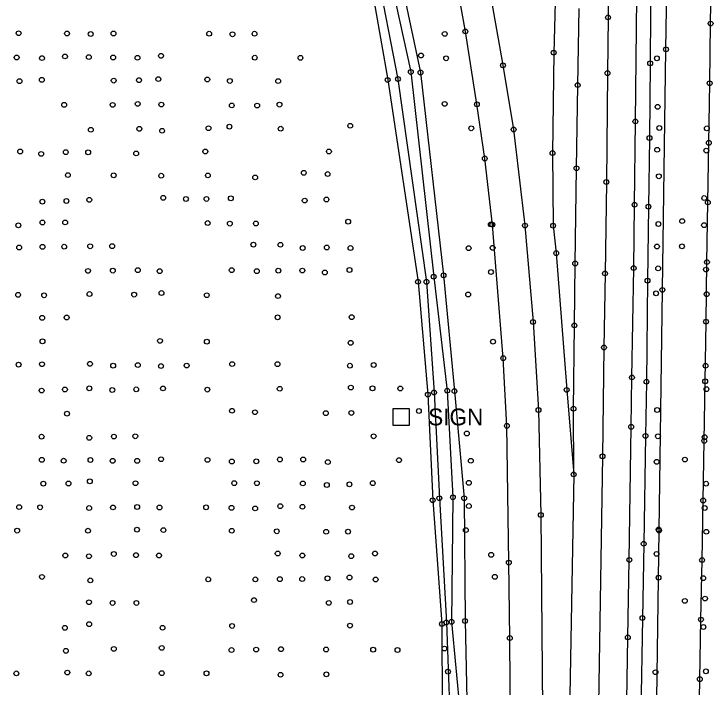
# Model space of a CAD drawing. Extents: x 20503438 to 20508873, y 7964251 to 7984667.
# Drawn here: x 20506370.9 to 20506661.3, y 7969202.7 to 7969482.5 of the extents above; entities that cross this region are included whole.
import ezdxf

# ---------------------------------------------------------------- set-up
doc = ezdxf.new("R2010")
doc.units = 0
for name, color, linetype in [('SurBreakLine', 7, 'Continuous'), ('SurConcreteSlab', 7, 'Continuous'), ('SurDrainageArrowDown', 7, 'Continuous'), ('SurDrainageArrowUp', 7, 'Continuous'), ('SurEdgeRoadPaved', 7, 'Continuous'), ('SurEdgeShoulderPaved', 7, 'Continuous'), ('SurGuardRailCable', 7, 'Continuous'), ('SurPointsNonDTM', 7, 'Continuous'), ('SurRoadPoints', 7, 'Continuous'), ('SurSurveyPoints', 7, 'Continuous')]:
    doc.layers.add(name, color=color, linetype=linetype)

msp = doc.modelspace()

# ---------------------------------------------------------------- linework, layer by layer
at = {"layer": 'SurBreakLine'}
for points in [[(20506618.14, 7969523.36), (20506617.67, 7969481.03), (20506617.43, 7969457.83), (20506616.96, 7969412.61), (20506616.41, 7969374.63), (20506615.97, 7969343.84), (20506615.38, 7969298.61), (20506613.68, 7969195.48), (20506612.84, 7969147.98), (20506612.67, 7969139.02), (20506612.29, 7969096.34), (20506611.74, 7969045.72), (20506611.38, 7969017.5), (20506610.7, 7968975.24), (20506609.9, 7968927.43)], [(20506526.38, 7969501.4), (20506535.77, 7969458.35), (20506545.25, 7969373.27), (20506550.88, 7969325.87), (20506553.23, 7969281.58), (20506552.68, 7969229.8), (20506556.22, 7969191.53), (20506555.93, 7969123.81), (20506558.38, 7969055.03)], [(20506530.55, 7969501.87), (20506539.77, 7969458.14), (20506549.36, 7969373.83), (20506553.86, 7969325.71), (20506557.91, 7969281.18), (20506558.28, 7969230.17), (20506559.1, 7969190.68), (20506560.16, 7969121.72), (20506560.98, 7969054.99)], [(20506518.36, 7969500.09), (20506526.15, 7969455.03), (20506538.74, 7969371.16), (20506542.8, 7969324.25), (20506544.83, 7969280.33), (20506548.66, 7969228.93), (20506548.82, 7969193.76), (20506548.24, 7969123.29), (20506548.83, 7969054.45)]]:
    msp.add_lwpolyline(points, dxfattribs=at)
at = {"layer": 'SurConcreteSlab'}
msp.add_lwpolyline([(20506564.49, 7969514.44), (20506574.01, 7969461.11), (20506578.45, 7969434.44), (20506583.17, 7969394.51), (20506586.51, 7969354.44), (20506588.8, 7969317.85), (20506589.77, 7969274.23), (20506590.63, 7969177.23), (20506591.64, 7969086.12), (20506591.92, 7969027.98), (20506592.58, 7968959.05), (20506592.8, 7968932.21), (20506593.59, 7968825.07), (20506593.73, 7968776.04), (20506594.33, 7968740.28), (20506595.27, 7968683.67)], dxfattribs=at)
at = {"layer": 'SurDrainageArrowDown'}
msp.add_lwpolyline([(20506653.71, 7968931.94), (20506653.76, 7968956.94), (20506653.81, 7968981.94), (20506653.87, 7969006.94), (20506653.92, 7969031.94), (20506653.97, 7969056.94), (20506654.02, 7969081.94), (20506654.08, 7969106.94), (20506654.43, 7969131.75), (20506654.89, 7969156.5), (20506655.35, 7969181.25), (20506655.81, 7969206), (20506656.26, 7969230.74), (20506656.72, 7969255.49), (20506657.18, 7969280.24), (20506657.62, 7969305), (20506658, 7969329.78), (20506658.38, 7969354.56), (20506658.75, 7969379.34), (20506659.13, 7969404.12), (20506659.51, 7969428.89), (20506659.89, 7969453.67), (20506660.27, 7969478.45), (20506660.63, 7969503.23)], dxfattribs=at)
at = {"layer": 'SurDrainageArrowUp'}
msp.add_lwpolyline([(20506438.1, 7969771.83), (20506443.35, 7969742.94), (20506462.68, 7969706.4), (20506478.32, 7969662.6), (20506496.28, 7969609.97), (20506512.32, 7969564.26), (20506521.33, 7969501.72), (20506530.41, 7969455.42), (20506542.25, 7969371.11), (20506545.39, 7969325.12), (20506547.61, 7969281.18), (20506550.51, 7969229.55), (20506551.89, 7969191.24), (20506551.28, 7969123.71), (20506552.43, 7969055.04)], dxfattribs=at)
at = {"layer": 'SurEdgeRoadPaved'}
for points in [[(20506621.49, 7968907.38), (20506621.92, 7968945.44), (20506622.44, 7968976.48), (20506623.13, 7969015.52), (20506623.63, 7969053.1), (20506623.96, 7969082.25), (20506624.47, 7969121.99), (20506624.91, 7969159.97), (20506625.3, 7969188.54), (20506625.87, 7969223.35), (20506626.51, 7969255.54), (20506627.28, 7969310.85), (20506627.6, 7969331.39), (20506628.32, 7969376.84), (20506628.68, 7969403.15), (20506629.02, 7969437.79), (20506629.57, 7969489.48)], [(20506595.72, 7969487.19), (20506595.11, 7969466.36), (20506594.59, 7969424.65), (20506594.85, 7969394.48), (20506596.15, 7969383.03), (20506600.49, 7969326.21), (20506603.4, 7969291.1), (20506600.36, 7969122.74), (20506600.06, 7969086.76), (20506599.49, 7969053.21), (20506599.36, 7969019.14), (20506598.62, 7968981.46), (20506598.4, 7968961.23), (20506597.81, 7968911.23), (20506596.74, 7968813.5), (20506596.12, 7968772.39), (20506595.63, 7968706.72), (20506595.11, 7968672.96), (20506595.06, 7968637.97), (20506594.54, 7968602.04), (20506594.11, 7968535.15), (20506593.63, 7968499.17)], [(20506603.4, 7969291.1), (20506603.32, 7969318.39), (20506603.68, 7969353.03), (20506604.02, 7969378.75), (20506604.55, 7969418.34), (20506605.06, 7969452.89), (20506605.62, 7969484.73)]]:
    msp.add_lwpolyline(points, dxfattribs=at)
at = {"layer": 'SurEdgeShoulderPaved'}
for points in [[(20506579.21, 7968920.08), (20506580.04, 7968948.94), (20506578.13, 7968975.95), (20506578.51, 7968997.69), (20506578.2, 7969027.13), (20506578.68, 7969043.72), (20506578.97, 7969057.63), (20506578.72, 7969080.47), (20506578.43, 7969086.41), (20506578.28, 7969089.38), (20506577.4, 7969107.2), (20506577.45, 7969146.63), (20506576.88, 7969223.07), (20506576.47, 7969254.43), (20506575.66, 7969311.26), (20506574.14, 7969339.42), (20506569.62, 7969394.88), (20506566.46, 7969422.38), (20506563.2, 7969444.91), (20506558.41, 7969475.22), (20506553.3, 7969503.59)], [(20506635.48, 7969504.27), (20506635.15, 7969461.94), (20506634.88, 7969430.9), (20506634.45, 7969402.36), (20506634.07, 7969371.62), (20506633.61, 7969329.61), (20506633.23, 7969307.1), (20506632.49, 7969262.27), (20506631.93, 7969231.4), (20506631.34, 7969191.98), (20506630.67, 7969146.89), (20506630.47, 7969127.19), (20506630.23, 7969104.68), (20506629.72, 7969073.79), (20506629.37, 7969033.53), (20506628.89, 7969008.02), (20506628.37, 7968979.45), (20506627.76, 7968942.11), (20506627.2, 7968902.1)]]:
    msp.add_lwpolyline(points, dxfattribs=at)
at = {"layer": 'SurGuardRailCable'}
msp.add_lwpolyline([(20506628.76, 7968467.84), (20506630.09, 7968567.83), (20506631.3, 7968667.82), (20506632.48, 7968767.82), (20506633.65, 7968867.81), (20506634.84, 7968967.8), (20506636.09, 7969067.8), (20506637.47, 7969167.79), (20506638.85, 7969267.78), (20506640.24, 7969367.77), (20506641.73, 7969467.75), (20506642.19, 7969501.7)], dxfattribs=at)
at = {"layer": 'SurPointsNonDTM'}
for centre in [(20506641.73, 7969467.75), (20506640.24, 7969367.77), (20506638.85, 7969267.78)]:
    msp.add_circle(centre, 1, dxfattribs=at)
at = {"layer": 'SurRoadPoints'}
msp.add_lwpolyline([(20506531.77, 7969311.54), (20506531.77, 7969311.54), (20506535.2, 7969311.54), (20506535.2, 7969318.4), (20506528.34, 7969318.4), (20506528.34, 7969311.54), (20506531.77, 7969311.54)], dxfattribs=at)
at = {"layer": 'SurSurveyPoints'}
for centre in [(20506617.67, 7969481.03), (20506660.27, 7969478.45), (20506372.86, 7969474.45), (20506392.97, 7969474.34), (20506402.8, 7969474.12), (20506412.25, 7969474.33), (20506452, 7969474.25), (20506461.71, 7969474.02), (20506470.86, 7969474.24), (20506549.84, 7969474.17), (20506558.41, 7969475.22), (20506392.12, 7969464.8), (20506402.03, 7969464.53), (20506432.01, 7969465.04), (20506539.97, 7969465.21), (20506595.11, 7969466.36), (20506372.06, 7969464.36), (20506382.58, 7969464.12), (20506412.14, 7969464.37), (20506422.22, 7969464.26), (20506470.93, 7969464.27), (20506489.91, 7969464.21), (20506550.4, 7969464.03), (20506635.15, 7969461.94), (20506637.97, 7969464.01), (20506574.01, 7969461.11), (20506535.77, 7969458.35), (20506539.77, 7969458.14), (20506617.43, 7969457.83), (20506373.21, 7969454.53), (20506382.51, 7969455.1), (20506412.36, 7969454.76), (20506422.87, 7969454.93), (20506430.9, 7969455.38), (20506451.22, 7969455.2), (20506460.6, 7969454.61), (20506480.67, 7969454.56), (20506526.15, 7969455.03), (20506530.41, 7969455.42), (20506605.06, 7969452.89), (20506659.89, 7969453.67), (20506391.79, 7969444.71), (20506411.91, 7969444.66), (20506422.32, 7969445.07), (20506432.13, 7969444.79), (20506461.39, 7969444.45), (20506471.95, 7969444.38), (20506481.2, 7969444.78), (20506549.82, 7969445.08), (20506563.2, 7969444.91), (20506638.26, 7969443.84), (20506460.41, 7969435.61), (20506510.6, 7969436), (20506629.02, 7969437.79), (20506402.86, 7969434.33), (20506422.98, 7969434.72), (20506432.45, 7969433.92), (20506451.71, 7969434.97), (20506481.71, 7969434.76), (20506560.86, 7969434.94), (20506578.45, 7969434.44), (20506638.96, 7969435.07), (20506658.72, 7969434.9), (20506634.88, 7969430.9), (20506659.51, 7969428.89), (20506373.52, 7969425.3), (20506382.23, 7969424.3), (20506392.44, 7969425.01), (20506401.73, 7969424.94), (20506421.69, 7969424.5), (20506450.42, 7969425.31), (20506501.74, 7969425.31), (20506594.59, 7969424.65), (20506638.09, 7969426.01), (20506658.48, 7969425.66), (20506566.46, 7969422.38), (20506604.55, 7969418.34), (20506393.33, 7969415.49), (20506412.34, 7969415.4), (20506432.09, 7969415.22), (20506451.48, 7969415.35), (20506491.28, 7969416.44), (20506501.2, 7969415.92), (20506471.11, 7969414.51), (20506616.96, 7969412.61), (20506638.78, 7969414.99), (20506382.73, 7969404.45), (20506392.71, 7969404.73), (20506402.21, 7969405.21), (20506432.92, 7969406.04), (20506442.35, 7969405.56), (20506450.86, 7969405.58), (20506461.01, 7969405.84), (20506491.68, 7969404.9), (20506500.7, 7969405.33), (20506657.62, 7969405.94), (20506659.13, 7969404.12), (20506628.68, 7969403.15), (20506634.45, 7969402.36), (20506382.74, 7969395.77), (20506392.18, 7969395.82), (20506451.39, 7969395.56), (20506460.58, 7969395.33), (20506471.42, 7969395.37), (20506509.71, 7969396.14), (20506568.97, 7969395), (20506569.62, 7969394.88), (20506638.6, 7969395.16), (20506648.44, 7969396.37), (20506372.75, 7969394.61), (20506583.17, 7969394.51), (20506594.85, 7969394.48), (20506657.55, 7969394.69), (20506470.37, 7969386.56), (20506481.6, 7969386.53), (20506373.07, 7969385.41), (20506382.77, 7969385.69), (20506391.81, 7969385.72), (20506402.57, 7969385.91), (20506411.72, 7969385.93), (20506490.84, 7969385.18), (20506500.84, 7969385.4), (20506510.69, 7969385.17), (20506559.76, 7969385.1), (20506569.73, 7969385.27), (20506637.98, 7969385.79), (20506648.37, 7969385.89), (20506596.15, 7969383.03), (20506604.02, 7969378.75), (20506658.75, 7969379.34), (20506401.66, 7969375.67), (20506411.99, 7969375.79), (20506422.36, 7969375.98), (20506431.45, 7969375.57), (20506461.36, 7969375.97), (20506471.8, 7969375.55), (20506480.72, 7969375.76), (20506490.7, 7969375.81), (20506500.05, 7969374.99), (20506510.29, 7969376.03), (20506569.04, 7969375.2), (20506616.41, 7969374.63), (20506628.32, 7969376.84), (20506638.47, 7969376.71), (20506658.34, 7969376.23), (20506545.25, 7969373.27), (20506549.36, 7969373.83), (20506634.07, 7969371.62), (20506538.74, 7969371.16), (20506542.25, 7969371.11), (20506402.31, 7969366.05), (20506420.84, 7969365.81), (20506432.19, 7969366.46), (20506559.57, 7969365.88), (20506637.62, 7969366.36), (20506658.62, 7969365.98), (20506372.64, 7969365.73), (20506383.44, 7969365.54), (20506451, 7969365.56), (20506480.59, 7969365.2), (20506382.62, 7969356.18), (20506392.8, 7969356.3), (20506480.43, 7969356.37), (20506511.18, 7969356.44), (20506586.51, 7969354.44), (20506658.38, 7969354.56), (20506603.68, 7969353.03), (20506382.77, 7969346.41), (20506431.6, 7969346.57), (20506451.01, 7969346.26), (20506510.76, 7969345.76), (20506569.91, 7969346.26), (20506615.97, 7969343.84), (20506382.56, 7969336.87), (20506402.48, 7969337.04), (20506461.54, 7969336.94), (20506480.36, 7969336.9), (20506574.14, 7969339.42), (20506372.85, 7969336.69), (20506412.13, 7969336.27), (20506422.39, 7969336.53), (20506431.99, 7969336.12), (20506442.66, 7969336.32), (20506510.46, 7969336.26), (20506520.34, 7969336.57), (20506658.18, 7969336.24), (20506627.6, 7969331.39), (20506633.61, 7969329.61), (20506658, 7969329.78), (20506382.41, 7969325.93), (20506392.09, 7969326.39), (20506402.22, 7969326.86), (20506411.75, 7969326.16), (20506421.71, 7969326.43), (20506432.83, 7969326.83), (20506451.26, 7969326.33), (20506481.31, 7969326.68), (20506510.83, 7969327.17), (20506519.82, 7969326.87), (20506531.38, 7969326.81), (20506550.88, 7969325.87), (20506553.86, 7969325.71), (20506600.49, 7969326.21), (20506658.54, 7969326.51), (20506542.8, 7969324.25), (20506545.39, 7969325.12), (20506461.48, 7969317.55), (20506471.02, 7969316.93), (20506500.44, 7969316.55), (20506511.06, 7969316.63), (20506539.11, 7969317.43), (20506588.8, 7969317.85), (20506603.32, 7969318.39), (20506638.06, 7969317.87), (20506392.95, 7969316.33), (20506575.66, 7969311.26), (20506627.28, 7969310.85), (20506559.03, 7969308.09), (20506382.4, 7969306.76), (20506402.2, 7969306.3), (20506412.44, 7969306.81), (20506421.31, 7969306.94), (20506520.3, 7969306.94), (20506633.23, 7969307.1), (20506638.39, 7969306.94), (20506657.62, 7969305), (20506657.78, 7969306.55), (20506382.5, 7969297.15), (20506391.56, 7969296.77), (20506402.69, 7969297.08), (20506411.92, 7969296.75), (20506422.11, 7969296.72), (20506432.03, 7969297.39), (20506451.3, 7969297.11), (20506461.42, 7969296.47), (20506471.58, 7969296.51), (20506481.38, 7969297.28), (20506491.02, 7969297.3), (20506501.3, 7969296.21), (20506530.86, 7969297), (20506560.66, 7969296.76), (20506615.38, 7969298.61), (20506637.85, 7969296.31), (20506649.6, 7969297.26), (20506603.4, 7969291.1), (20506603.4, 7969291.1), (20506402.42, 7969288.22), (20506421.42, 7969287.41), (20506462.42, 7969287.45), (20506471.82, 7969287.41), (20506519.94, 7969287.43), (20506559.84, 7969287.59), (20506383.13, 7969287.23), (20506393.56, 7969287.31), (20506490.91, 7969287.34), (20506500.89, 7969286.7), (20506510.26, 7969286.97), (20506658.4, 7969287.22), (20506544.83, 7969280.33), (20506547.61, 7969281.18), (20506553.23, 7969281.58), (20506557.91, 7969281.18), (20506657.18, 7969280.24), (20506373.08, 7969277.51), (20506381.78, 7969277.42), (20506402.17, 7969277.1), (20506412.05, 7969277.37), (20506422.09, 7969277.54), (20506431.38, 7969277.35), (20506450.73, 7969277.41), (20506461.28, 7969277.19), (20506471.09, 7969276.95), (20506481.53, 7969277.89), (20506490.73, 7969277.65), (20506511.33, 7969277.31), (20506559.83, 7969277.93), (20506657.82, 7969277.12), (20506589.77, 7969274.23), (20506372.25, 7969267.73), (20506401.68, 7969267.68), (20506422.01, 7969268.12), (20506432.99, 7969267.94), (20506461.38, 7969267.66), (20506480.08, 7969267.45), (20506500.58, 7969267.26), (20506509.69, 7969267.28), (20506558.61, 7969267.94), (20506638.7, 7969268.19), (20506658.49, 7969267.25), (20506632.49, 7969262.27), (20506392.26, 7969257.4), (20506402.06, 7969257.08), (20506412.41, 7969258.03), (20506421.61, 7969257.51), (20506431.15, 7969257.37), (20506480.48, 7969258.21), (20506490.71, 7969257.39), (20506511, 7969257.11), (20506520.88, 7969258.2), (20506569.11, 7969257.67), (20506626.51, 7969255.54), (20506637.82, 7969258.05), (20506656.72, 7969255.49), (20506576.47, 7969254.43), (20506382.55, 7969248.48), (20506402.64, 7969247.05), (20506451.62, 7969247.46), (20506471.2, 7969247.46), (20506481.37, 7969247.54), (20506490.61, 7969247.59), (20506501.15, 7969247.9), (20506510.27, 7969248.25), (20506521.13, 7969247.4), (20506570.64, 7969248.53), (20506638.65, 7969248.16), (20506657.2, 7969247.95), (20506470.62, 7969238.85), (20506510.52, 7969238.07), (20506649.57, 7969238.52), (20506657.96, 7969239.49), (20506402.09, 7969237.96), (20506411.88, 7969237.66), (20506421.79, 7969237.66), (20506501.67, 7969237.69), (20506550.51, 7969229.55), (20506552.68, 7969229.8), (20506558.28, 7969230.17), (20506631.93, 7969231.4), (20506656.26, 7969230.74), (20506392.08, 7969227.33), (20506402.16, 7969228.84), (20506432.64, 7969227.36), (20506461.53, 7969228.11), (20506510.5, 7969228.24), (20506548.66, 7969228.93), (20506657.28, 7969227.66), (20506576.88, 7969223.07), (20506625.87, 7969223.35), (20506392.49, 7969217.78), (20506412.41, 7969218.56), (20506432.3, 7969218.98), (20506461.28, 7969218.08), (20506471.51, 7969218.28), (20506481.83, 7969218.47), (20506500.57, 7969218.3), (20506520.12, 7969218.24), (20506530.23, 7969218.12), (20506549.71, 7969218.7), (20506551.17, 7969209.1), (20506658.32, 7969209.24), (20506371.93, 7969208.39), (20506393.09, 7969208.73), (20506401.97, 7969208.39), (20506432.3, 7969208.48), (20506450.88, 7969208.41), (20506481.65, 7969207.81), (20506500.68, 7969207.99), (20506637.4, 7969208.87), (20506655.81, 7969206)]:
    msp.add_circle(centre, 1, dxfattribs=at)

# ---------------------------------------------------------------- texts
at = {"layer": 'SurRoadPoints'}
msp.add_text('SIGN', height=6.995, rotation=360, dxfattribs=at).set_placement((20506542.98, 7969311.47))

doc.saveas('drawing.dxf')
